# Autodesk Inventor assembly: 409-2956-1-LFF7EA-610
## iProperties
Created: 2010-06
Part Number: 409-2956-1-LFF7EA-610
Document SubType Name: Weldment
Designer: S. Boerckel
Weld Material: Welded Aluminum-6061
Mass: 140760 g
Surface Area: 24156.6 cm^2
Volume: 17907 cm^3
Density: 7.86062 g/cm^3
Description: PUMP MOUNT
Material: WELDMENT
SMR: =<Material>
Length: 47.000 in
Wide: 17.000 in
Thickness: 6.438 in
Author: S. Boerckel
Revision Number: 0
Subject: DEMIN WATER FORWARDING PUMP SKID-7EA
